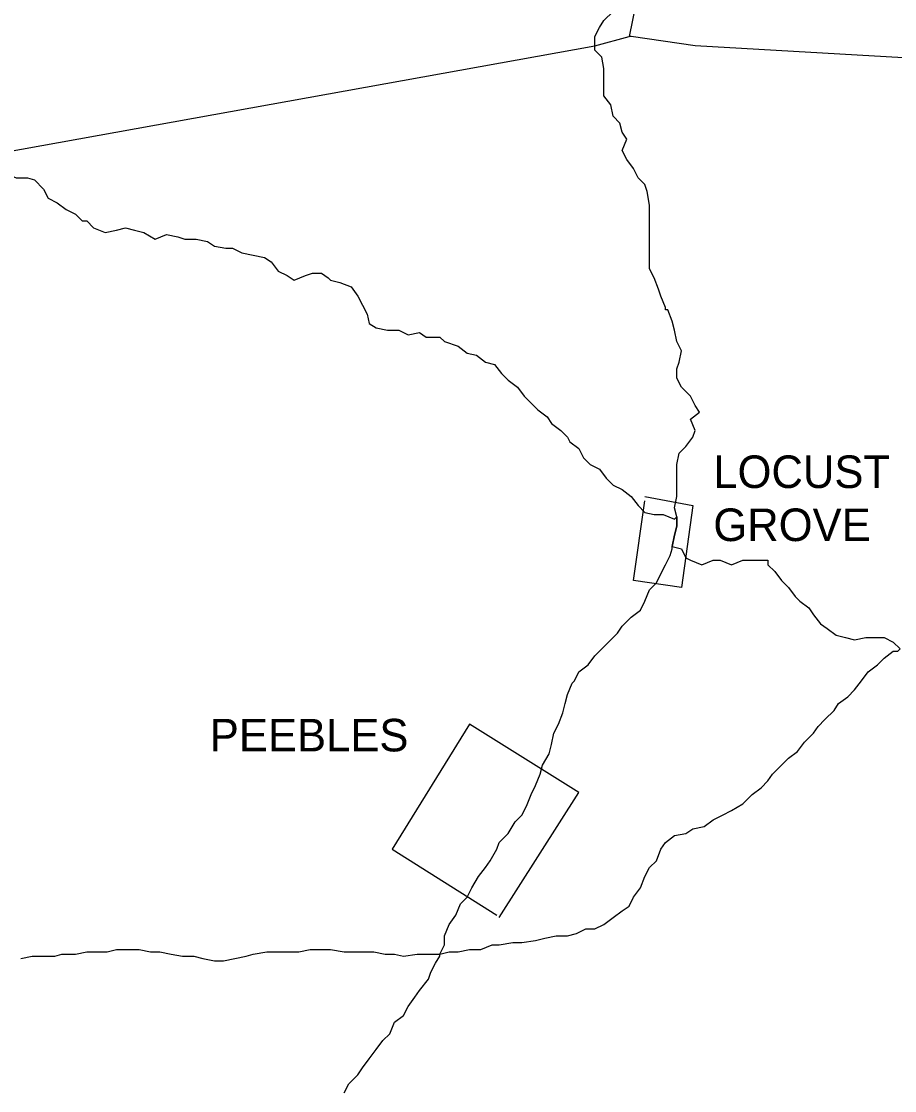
# Model space of a CAD drawing. Extents: x 0 to 40.2, y 0 to 22.
# Drawn here: x 4.298 to 4.821, y 17.238 to 17.878 of the extents above; entities that cross this region are included whole.
import ezdxf

# ---------------------------------------------------------------- set-up
doc = ezdxf.new("R2010")
doc.units = 0
doc.layers.add('Default', color=7, linetype='Continuous')

msp = doc.modelspace()

# ---------------------------------------------------------------- linework, layer by layer
at = {"layer": 'Default'}
for points in [[(4.7818, 18.51094), (4.75726, 18.37868), (4.73681, 18.26143), (4.72318, 18.18235), (4.70818, 18.10191), (4.69182, 18.01601), (4.66182, 17.86877)], [(4.64137, 17.86331), (4.64137, 17.86877), (4.6441, 17.87422), (4.64682, 17.87831), (4.65228, 17.88376), (4.65637, 17.88922), (4.66182, 17.89331), (4.66182, 17.89876), (4.65909, 17.90421), (4.66182, 17.90967), (4.65773, 17.91512), (4.65773, 17.92194), (4.66046, 17.92739), (4.66182, 17.93421), (4.66182, 17.94239), (4.66182, 17.94648), (4.66182, 17.94648)], [(3.64607, 17.72152), (3.69652, 17.71879), (3.86149, 17.71334), (3.95284, 17.73242), (4.2637, 17.79514), (4.64137, 17.86331), (4.66182, 17.86877)], [(4.91269, 17.85104), (4.70136, 17.86331), (4.66318, 17.86877), (4.66182, 17.86877)], [(4.68364, 17.70652), (4.68091, 17.71334), (4.67955, 17.71743), (4.67682, 17.72424), (4.67409, 17.7297), (4.67409, 17.73651), (4.67409, 17.74333), (4.67409, 17.75015), (4.67409, 17.7556), (4.67409, 17.76242), (4.67409, 17.76787), (4.67273, 17.77605), (4.67137, 17.78014), (4.66728, 17.78423), (4.66455, 17.78969), (4.66046, 17.79514), (4.65773, 17.80059), (4.66046, 17.80741), (4.65773, 17.8115), (4.65637, 17.81696), (4.65228, 17.82105), (4.65091, 17.82786), (4.64682, 17.83332), (4.64682, 17.83741), (4.64682, 17.84422), (4.64682, 17.84968), (4.64546, 17.85649), (4.64137, 17.86058), (4.64137, 17.86195), (4.64137, 17.86331)], [(4.26507, 17.79378), (4.27052, 17.79241), (4.27734, 17.79105), (4.28279, 17.78832), (4.28824, 17.78696), (4.29506, 17.78423), (4.30188, 17.78423), (4.30597, 17.78287), (4.31142, 17.77742), (4.31415, 17.77196), (4.3196, 17.76924), (4.32506, 17.76515), (4.33051, 17.76242), (4.3346, 17.75833), (4.33733, 17.75833)], [(4.33733, 17.75833), (4.34142, 17.75424), (4.34823, 17.75151), (4.35505, 17.75287), (4.36051, 17.75424), (4.36596, 17.75287), (4.37141, 17.75151), (4.37823, 17.74742), (4.38505, 17.75015), (4.39186, 17.74878), (4.39595, 17.74742), (4.40277, 17.74742), (4.40959, 17.74606), (4.41368, 17.74333), (4.4205, 17.74197), (4.42459, 17.74197)], [(4.42459, 17.74197), (4.43004, 17.73924), (4.43686, 17.73788), (4.44367, 17.73651), (4.44776, 17.73379), (4.45185, 17.72833), (4.45731, 17.72561), (4.4614, 17.72288), (4.46822, 17.72561), (4.47231, 17.72697), (4.47776, 17.72697), (4.48185, 17.72424), (4.48321, 17.72288)], [(4.48321, 17.72288), (4.48867, 17.72152), (4.49548, 17.71879), (4.49957, 17.71334), (4.5023, 17.70788), (4.50503, 17.70243), (4.50639, 17.69697), (4.51048, 17.69425), (4.5173, 17.69288), (4.52412, 17.69288), (4.52957, 17.69016), (4.53639, 17.69152), (4.54048, 17.68879), (4.54184, 17.68879), (4.54184, 17.68879)], [(4.69045, 17.58108), (4.68909, 17.58654), (4.69045, 17.59335), (4.69045, 17.59881), (4.69045, 17.60699), (4.69045, 17.61244), (4.69182, 17.61926), (4.69591, 17.62335), (4.7, 17.6288), (4.70136, 17.63289), (4.69863, 17.63971), (4.70409, 17.6438), (4.70136, 17.64789), (4.69863, 17.65334), (4.69318, 17.6588), (4.69045, 17.66425), (4.69045, 17.66971), (4.69182, 17.6738), (4.69318, 17.68061), (4.69045, 17.68607), (4.68909, 17.69288), (4.68773, 17.69834), (4.685, 17.70515), (4.68364, 17.70515), (4.68364, 17.70652)], [(4.54184, 17.68879), (4.54866, 17.68879), (4.55138, 17.68607), (4.55956, 17.68334), (4.56502, 17.67925), (4.57047, 17.67789), (4.57593, 17.6738), (4.58138, 17.67243), (4.58547, 17.66698), (4.58956, 17.66289), (4.59501, 17.6588), (4.5991, 17.65334), (4.60319, 17.64925), (4.60728, 17.64516), (4.61274, 17.64107), (4.61547, 17.63698), (4.62092, 17.63289), (4.62501, 17.6288), (4.62501, 17.6288), (4.62637, 17.62608)], [(4.62637, 17.62608), (4.63183, 17.62199), (4.63455, 17.61653), (4.63864, 17.61244), (4.6441, 17.60972), (4.64819, 17.60426), (4.65228, 17.60017), (4.65773, 17.59744), (4.66318, 17.59335), (4.66728, 17.5879), (4.67137, 17.58381), (4.67682, 17.58245), (4.68227, 17.58245), (4.68909, 17.57972), (4.69045, 17.58108)], [(4.67137, 17.59335), (4.7, 17.5879), (4.69318, 17.53882), (4.66455, 17.54291), (4.67137, 17.59063)], [(4.69045, 17.58108), (4.69045, 17.57563), (4.68909, 17.57018), (4.68773, 17.56336)], [(4.68773, 17.56336), (4.68909, 17.57018), (4.69045, 17.57563), (4.69045, 17.58108)], [(4.6291, 17.48292), (4.63183, 17.48837), (4.63728, 17.49246), (4.64137, 17.49791), (4.64546, 17.50201), (4.64955, 17.5061), (4.655, 17.51155), (4.65773, 17.51564), (4.66318, 17.52109), (4.66864, 17.52518), (4.67137, 17.53064), (4.67409, 17.53745), (4.67818, 17.54154), (4.68091, 17.547), (4.68364, 17.55245), (4.68636, 17.55791), (4.68773, 17.562), (4.68773, 17.56336)], [(4.68773, 17.56336), (4.69318, 17.562), (4.69591, 17.55654), (4.69863, 17.55518), (4.70545, 17.55245), (4.71227, 17.55518), (4.71636, 17.55518), (4.72318, 17.55245), (4.72999, 17.55518), (4.73681, 17.55518), (4.74226, 17.55518), (4.74499, 17.55518), (4.74499, 17.55245)], [(4.74499, 17.55245), (4.74908, 17.54836), (4.75317, 17.54291), (4.75726, 17.53882), (4.76135, 17.53336), (4.76408, 17.53064), (4.76953, 17.52655), (4.77226, 17.52246), (4.77635, 17.517), (4.78044, 17.51428), (4.78589, 17.51019), (4.79135, 17.50882), (4.7968, 17.50746), (4.80362, 17.50882), (4.81043, 17.50882), (4.81452, 17.50882), (4.81998, 17.5061), (4.82407, 17.50201), (4.82407, 17.50201)], [(4.73545, 17.41475), (4.7409, 17.41884), (4.74499, 17.42293), (4.74772, 17.42702), (4.75317, 17.43247), (4.75726, 17.43656), (4.76271, 17.44065), (4.7668, 17.4461), (4.77226, 17.45156), (4.77499, 17.45565), (4.77908, 17.45974), (4.78453, 17.46519), (4.78726, 17.46928), (4.79271, 17.47337), (4.7968, 17.47746), (4.80089, 17.48292), (4.80498, 17.48837), (4.81043, 17.49246), (4.81452, 17.49655), (4.81998, 17.50064), (4.82271, 17.50064), (4.82407, 17.50201)], [(4.58411, 17.38611), (4.58956, 17.39157), (4.59365, 17.39839), (4.59774, 17.40248), (4.60047, 17.40793), (4.60319, 17.41475), (4.60592, 17.4202), (4.60865, 17.42702), (4.61001, 17.43247), (4.6141, 17.43929), (4.61547, 17.44474), (4.61683, 17.45156), (4.61956, 17.45701), (4.62228, 17.46383), (4.62365, 17.46928), (4.62501, 17.47474), (4.62774, 17.48155), (4.6291, 17.48292)], [(4.58411, 17.34112), (4.63183, 17.41611), (4.56638, 17.45701), (4.52003, 17.38202), (4.58274, 17.34249)], [(4.63046, 17.33158), (4.63592, 17.3343), (4.64137, 17.3343), (4.64682, 17.33703), (4.65228, 17.34112), (4.65773, 17.34521), (4.66182, 17.34794), (4.66455, 17.35339), (4.66864, 17.35885), (4.67137, 17.36566), (4.67409, 17.37112), (4.67818, 17.37521), (4.68091, 17.38202), (4.68364, 17.38611), (4.68909, 17.3902), (4.69591, 17.39157), (4.7, 17.3943), (4.70681, 17.39566), (4.71227, 17.39975), (4.71772, 17.40248), (4.72318, 17.4052), (4.72999, 17.40929), (4.73272, 17.41202), (4.73545, 17.41475), (4.73545, 17.41475)], [(4.54866, 17.31931), (4.55138, 17.32476), (4.55138, 17.33021), (4.55411, 17.33703), (4.5582, 17.34249), (4.56093, 17.3493), (4.56502, 17.35339), (4.56775, 17.35885), (4.57184, 17.36566), (4.57593, 17.37112), (4.57865, 17.37521), (4.58274, 17.38202), (4.58411, 17.38611), (4.58411, 17.38611)], [(4.54866, 17.31931), (4.55411, 17.32067), (4.55956, 17.32067), (4.56638, 17.32203), (4.5732, 17.32203), (4.58002, 17.32476), (4.58411, 17.32476), (4.59229, 17.32612), (4.59774, 17.32612), (4.60592, 17.32749), (4.61137, 17.32885), (4.61819, 17.33021), (4.62501, 17.33021), (4.63046, 17.33158)], [(4.29779, 17.31658), (4.30461, 17.31794), (4.31142, 17.31794), (4.31824, 17.31794), (4.32233, 17.31931), (4.33051, 17.31931), (4.33733, 17.32067), (4.34414, 17.32067), (4.3496, 17.32067), (4.35505, 17.32203), (4.36187, 17.32203), (4.36869, 17.32203), (4.3755, 17.32067), (4.38096, 17.32067), (4.38777, 17.31931), (4.39459, 17.31794), (4.40141, 17.31794), (4.40686, 17.31658), (4.41368, 17.31522), (4.41913, 17.31522), (4.42595, 17.31658), (4.43277, 17.31794), (4.43686, 17.31931), (4.44504, 17.32067), (4.45049, 17.32067), (4.45867, 17.32067), (4.46413, 17.32067), (4.47094, 17.32203), (4.47776, 17.32203), (4.48321, 17.32203), (4.49139, 17.32067), (4.49548, 17.32067), (4.5023, 17.32067), (4.50912, 17.32067), (4.51594, 17.31931), (4.52139, 17.31931), (4.52684, 17.31794), (4.53502, 17.31931), (4.54184, 17.31931), (4.54866, 17.31931), (4.54866, 17.31931)], [(4.49139, 17.23614), (4.49412, 17.24159), (4.49957, 17.24705), (4.5023, 17.25114), (4.50639, 17.25659), (4.51048, 17.26204), (4.51457, 17.2675), (4.51866, 17.27159), (4.52139, 17.2784), (4.52684, 17.28249), (4.52957, 17.28795), (4.53366, 17.2934), (4.53639, 17.29749), (4.54184, 17.30431), (4.5432, 17.3084), (4.54593, 17.31385), (4.54866, 17.31794), (4.54866, 17.31931)]]:
    msp.add_lwpolyline(points, dxfattribs=at)

# ---------------------------------------------------------------- texts
for s, p in [('LOCUST', (4.71227, 17.59839)), ('GROVE', (4.71227, 17.56662)), ('PEEBLES', (4.41095, 17.44065))]:
    msp.add_text(s, height=0.019502, dxfattribs=at).set_placement(p)

doc.saveas('drawing.dxf')
